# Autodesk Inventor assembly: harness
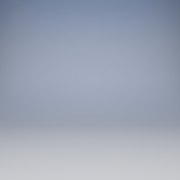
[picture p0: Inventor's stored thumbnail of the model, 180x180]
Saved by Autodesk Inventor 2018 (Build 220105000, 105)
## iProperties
HarnessSettings: <HarnessSettings><Defaults><Segments><Diameter value="0.200 in" fromwires="True"/><Offset value="0.100 in"/><ColorStyle value="Blue"/><BendRadius value="19" fro
Control State: 0
Master: False
Checked Out: False
Part Number: harness
Document SubType Name: Assembly
Created: 2002-07
Material: Ogólny
Shininess: 64.0
Length Units: 11272
Angle Units: 11279
Time Units: 11290
Mass Units: 11286
Length Display Precision: 3
Angle Display Precision: 2
Compacted: True
Density: 0.0
Volumn: 0.0
Area: 0.0
PropertySet Name: Model Information
HarnessSettings: <HarnessSettings><Defaults><Segments><Diameter value="0.200 in" fromwires="True"/><Offset value="0.100 in"/><ColorStyle value="Niebieska — farba ścienna — lśnią
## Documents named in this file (1)
- C:\Users\Joffi\Desktop\Templates.Base\Cable & Harness\harness.iam
